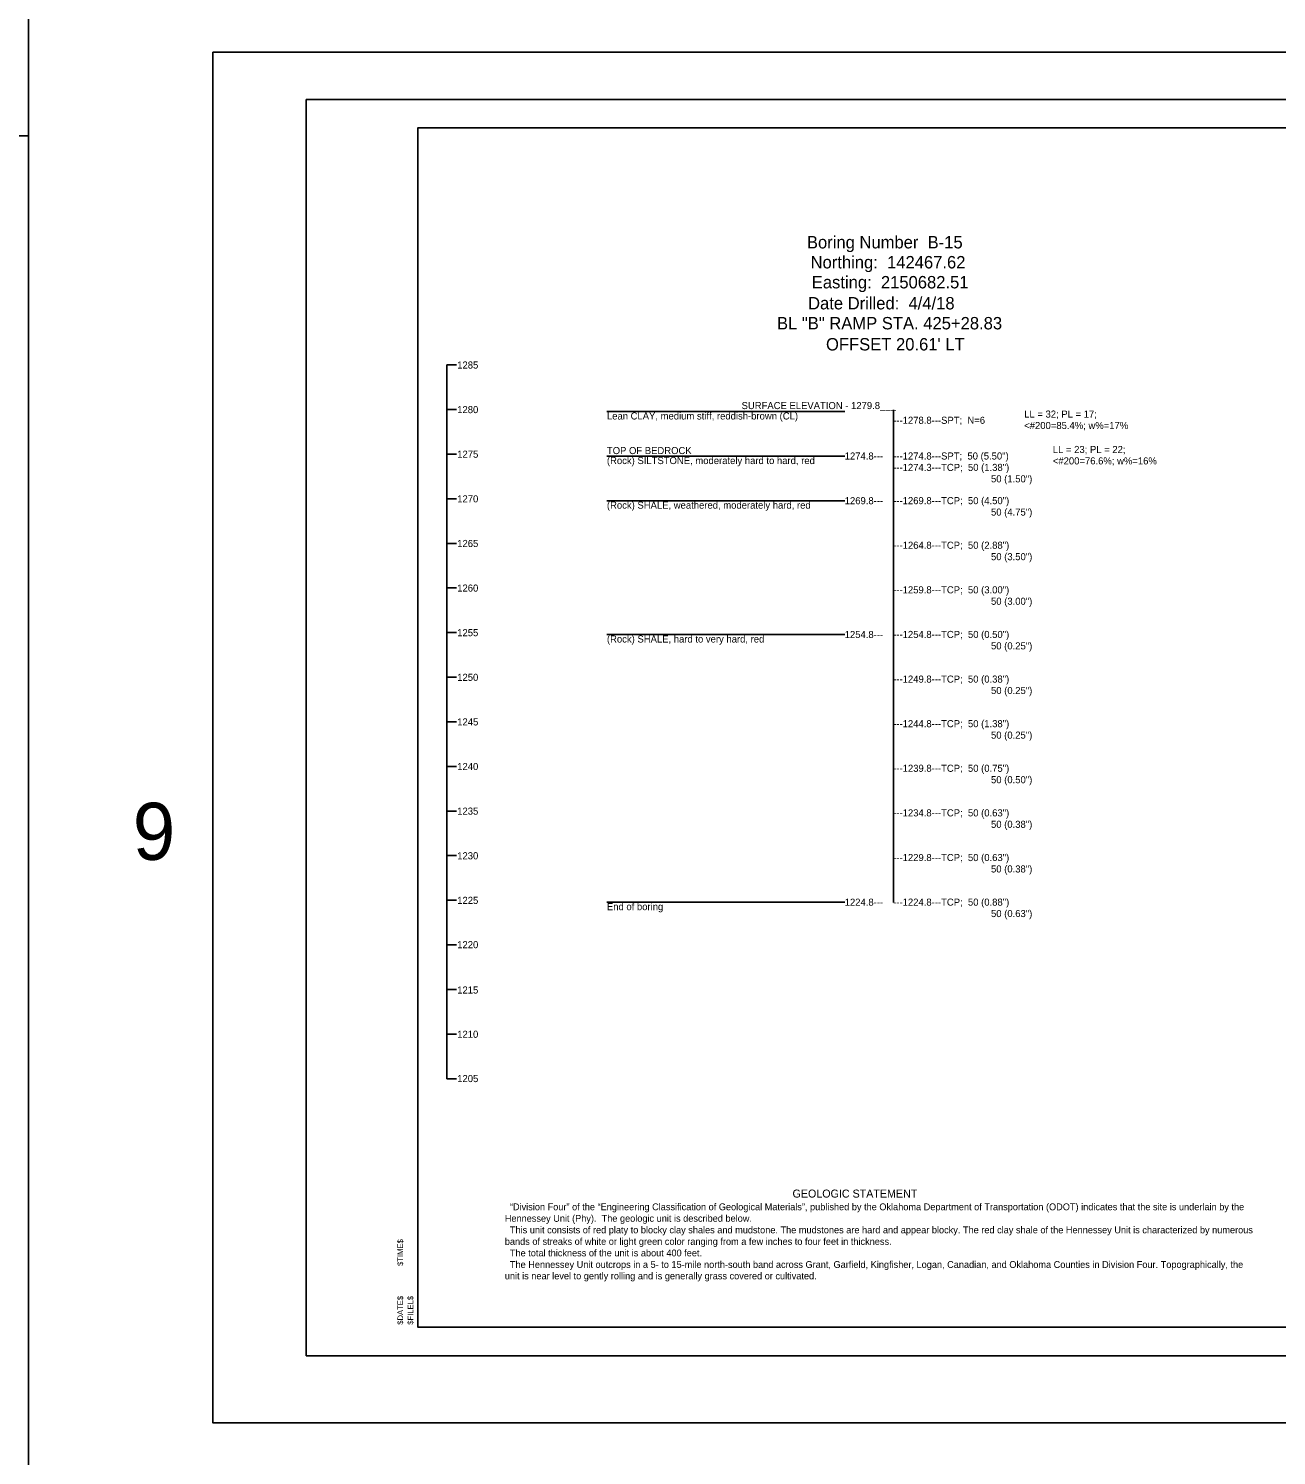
# Model space of a CAD drawing. Extents: x 2150162 to 2150245, y 143729 to 143865.
# Drawn here: x 2150203.4 to 2150225.25, y 143761.23 to 143786.22 of the extents above; entities that cross this region are included whole.
import ezdxf

# ---------------------------------------------------------------- set-up
doc = ezdxf.new("R2010")
doc.units = 0
for name, color, linetype in [('Default', 7, 'Continuous'), ('S', 7, 'Continuous'), ('SHT_Plot_Shape_Full', 7, 'Continuous'), ('SHT_Plot_Shape_Half', 7, 'Continuous'), ('SHT_Plot_Stamp', 7, 'Continuous'), ('SHT_Sheet_Border', 7, 'Continuous'), ('Text', 7, 'Continuous')]:
    doc.layers.add(name, color=color, linetype=linetype)

# ---------------------------------------------------------------- blocks, each defined once
blk = doc.blocks.new('Stamp_Plot_Stamp')
at = {"layer": 'SHT_Plot_Stamp'}
for s, p in [('$TIME$', (1.695, 1.572)), ('$DATE$', (1.695, 0.542)), ('$FILEL$', (1.873, 0.542))]:
    blk.add_text(s, height=0.1, rotation=90, dxfattribs=at).set_placement(p)

msp = doc.modelspace()

# ---------------------------------------------------------------- linework, layer by layer
at = {"layer": 'Default'}
msp.add_line((2150210.725, 143767.83), (2150210.725, 143780.33), dxfattribs=at)
for points in [[(2150210.725, 143780.33), (2150210.892, 143780.33)], [(2150210.725, 143779.549), (2150210.892, 143779.549)], [(2150213.527, 143779.515), (2150217.694, 143779.515)], [(2150218.543, 143779.543), (2150218.543, 143770.916)], [(2150210.725, 143778.767), (2150210.892, 143778.767)], [(2150213.527, 143778.734), (2150217.694, 143778.734)], [(2150210.725, 143777.986), (2150210.892, 143777.986)], [(2150210.725, 143777.986), (2150210.892, 143777.986)], [(2150213.527, 143777.952), (2150217.694, 143777.952)], [(2150210.725, 143777.205), (2150210.892, 143777.205)], [(2150210.725, 143776.424), (2150210.892, 143776.424)], [(2150210.725, 143775.642), (2150210.892, 143775.642)], [(2150213.527, 143775.609), (2150217.694, 143775.609)], [(2150210.725, 143774.861), (2150210.892, 143774.861)], [(2150210.725, 143774.08), (2150210.892, 143774.08)], [(2150210.725, 143773.299), (2150210.892, 143773.299)], [(2150210.725, 143772.517), (2150210.892, 143772.517)], [(2150210.725, 143771.736), (2150210.892, 143771.736)], [(2150210.725, 143770.955), (2150210.892, 143770.955)], [(2150213.527, 143770.921), (2150217.694, 143770.921)], [(2150210.725, 143770.174), (2150210.892, 143770.174)], [(2150210.725, 143769.392), (2150210.892, 143769.392)], [(2150210.725, 143768.611), (2150210.892, 143768.611)], [(2150210.725, 143767.83), (2150210.892, 143767.83)]]:
    msp.add_lwpolyline(points, dxfattribs=at)
at = {"layer": 'S'}
for points in [[(2150203.404, 143865.061), (2150245.24, 143865.061), (2150245.24, 143729.315), (2150203.404, 143729.315)], [(2150161.568, 143784.341), (2150203.404, 143784.341), (2150203.404, 143729.315), (2150161.568, 143729.315)]]:
    msp.add_lwpolyline(points, close=True, dxfattribs=at)
at = {"layer": 'SHT_Plot_Shape_Full'}
msp.add_lwpolyline([(2150206.628, 143785.804), (2150242.628, 143785.804), (2150242.628, 143761.804), (2150206.628, 143761.804)], close=True, dxfattribs=at)
at = {"layer": 'SHT_Plot_Shape_Half'}
msp.add_lwpolyline([(2150208.265, 143784.979), (2150242.265, 143784.979), (2150242.265, 143762.979), (2150208.265, 143762.979)], close=True, dxfattribs=at)
at = {"layer": 'SHT_Sheet_Border'}
msp.add_lwpolyline([(2150241.715, 143763.479), (2150210.215, 143763.479), (2150210.215, 143784.479), (2150241.715, 143784.479)], close=True, dxfattribs=at)

# ---------------------------------------------------------------- block references
at = {"layer": 'SHT_Plot_Stamp'}
msp.add_blockref('Stamp_Plot_Stamp', (2150208.265, 143762.979), dxfattribs=at)

# ---------------------------------------------------------------- texts
at = {"layer": 'Default'}
for s, height, p in [('Boring Number  B-15', 0.217, (2150217.028, 143782.37)), ('Northing:  142467.62', 0.217, (2150217.092, 143782.02)), ('Easting:  2150682.51', 0.217, (2150217.113, 143781.67)), ('Date Drilled:  4/4/18', 0.217, (2150217.048, 143781.302)), ('BL "B" RAMP STA. 425+28.83', 0.217, (2150216.504, 143780.952)), ("OFFSET 20.61' LT", 0.217, (2150217.362, 143780.583)), ('1285', 0.124, (2150210.907, 143780.266)), ('1280', 0.124, (2150210.907, 143779.485)), ('SURFACE ELEVATION - 1279.8___', 0.124, (2150215.884, 143779.556)), ('Lean CLAY, medium stiff, reddish-brown (CL)', 0.124, (2150213.527, 143779.374)), ('---1278.8---SPT;  N=6', 0.124, (2150218.538, 143779.298)), ('LL = 32; PL = 17;', 0.124, (2150220.831, 143779.407)), ('<#200=85.4%; w%=17%', 0.124, (2150220.831, 143779.207)), ('TOP OF BEDROCK', 0.124, (2150213.527, 143778.768)), ('LL = 23; PL = 22;', 0.124, (2150221.332, 143778.787)), ('1275', 0.124, (2150210.907, 143778.704)), ('(Rock) SILTSTONE, moderately hard to hard, red', 0.124, (2150213.527, 143778.593)), ('1274.8---', 0.124, (2150217.689, 143778.672)), ('---1274.8---SPT;  50 (5.50")', 0.124, (2150218.538, 143778.673)), ('<#200=76.6%; w%=16%', 0.124, (2150221.332, 143778.587)), ('---1274.3---TCP;  50 (1.38")', 0.124, (2150218.538, 143778.473)), ('50 (1.50")', 0.124, (2150220.25, 143778.273)), ('1270', 0.124, (2150210.907, 143777.922)), ('(Rock) SHALE, weathered, moderately hard, red', 0.124, (2150213.527, 143777.812)), ('1269.8---', 0.124, (2150217.689, 143777.89)), ('---1269.8---TCP;  50 (4.50")', 0.124, (2150218.538, 143777.891)), ('50 (4.75")', 0.124, (2150220.25, 143777.691)), ('1265', 0.124, (2150210.907, 143777.141)), ('---1264.8---TCP;  50 (2.88")', 0.124, (2150218.538, 143777.11)), ('50 (3.50")', 0.124, (2150220.25, 143776.91)), ('1260', 0.124, (2150210.907, 143776.36)), ('---1259.8---TCP;  50 (3.00")', 0.124, (2150218.538, 143776.329)), ('50 (3.00")', 0.124, (2150220.25, 143776.129)), ('1255', 0.124, (2150210.907, 143775.579)), ('1254.8---', 0.124, (2150217.689, 143775.547)), ('---1254.8---TCP;  50 (0.50")', 0.124, (2150218.538, 143775.548)), ('(Rock) SHALE, hard to very hard, red', 0.124, (2150213.527, 143775.468)), ('50 (0.25")', 0.124, (2150220.25, 143775.348)), ('1250', 0.124, (2150210.907, 143774.797)), ('---1249.8---TCP;  50 (0.38")', 0.124, (2150218.538, 143774.766)), ('50 (0.25")', 0.124, (2150220.25, 143774.566)), ('1245', 0.124, (2150210.907, 143774.016)), ('---1244.8---TCP;  50 (1.38")', 0.124, (2150218.538, 143773.985)), ('50 (0.25")', 0.124, (2150220.25, 143773.785)), ('1240', 0.124, (2150210.907, 143773.235)), ('---1239.8---TCP;  50 (0.75")', 0.124, (2150218.538, 143773.204)), ('50 (0.50")', 0.124, (2150220.25, 143773.004)), ('1235', 0.124, (2150210.907, 143772.454)), ('---1234.8---TCP;  50 (0.63")', 0.124, (2150218.538, 143772.423)), ('50 (0.38")', 0.124, (2150220.25, 143772.223)), ('1230', 0.124, (2150210.907, 143771.672)), ('---1229.8---TCP;  50 (0.63")', 0.124, (2150218.538, 143771.641)), ('50 (0.38")', 0.124, (2150220.25, 143771.441)), ('1225', 0.124, (2150210.907, 143770.891)), ('End of boring', 0.124, (2150213.527, 143770.781)), ('1224.8---', 0.124, (2150217.689, 143770.859)), ('---1224.8---TCP;  50 (0.88")', 0.124, (2150218.538, 143770.86)), ('50 (0.63")', 0.124, (2150220.25, 143770.66)), ('1220', 0.124, (2150210.907, 143770.115)), ('1215', 0.124, (2150210.907, 143769.321)), ('1210', 0.124, (2150210.907, 143768.546)), ('1205', 0.124, (2150210.907, 143767.77))]:
    msp.add_text(s, height=height, dxfattribs=at).set_placement(p)
at = {"layer": 'S'}
msp.add_text('9', height=1, dxfattribs=at).set_placement((2150205.228, 143771.662))
at = {"layer": 'Text'}
for s, height, p in [('GEOLOGIC STATEMENT', 0.14, (2150216.776, 143765.748)), ('  “Division Four” of the “Engineering Classification of Geological Materials”, published by the Oklahoma Department of Transportation (ODOT) indicates that the site is underlain by the ', 0.12, (2150211.74, 143765.526)), ('Hennessey Unit (Phy).  The geologic unit is described below. ', 0.12, (2150211.74, 143765.324)), ('  This unit consists of red platy to blocky clay shales and mudstone. The mudstones are hard and appear blocky. The red clay shale of the Hennessey Unit is characterized by numerous ', 0.12, (2150211.74, 143765.122)), ('bands of streaks of white or light green color ranging from a few inches to four feet in thickness. ', 0.12, (2150211.74, 143764.92)), ('  The total thickness of the unit is about 400 feet.', 0.12, (2150211.74, 143764.718)), ('  The Hennessey Unit outcrops in a 5- to 15-mile north-south band across Grant, Garfield, Kingfisher, Logan, Canadian, and Oklahoma Counties in Division Four. Topographically, the ', 0.12, (2150211.74, 143764.516)), ('unit is near level to gently rolling and is generally grass covered or cultivated.', 0.12, (2150211.74, 143764.316))]:
    msp.add_text(s, height=height, dxfattribs=at).set_placement(p)

doc.saveas('drawing.dxf')
